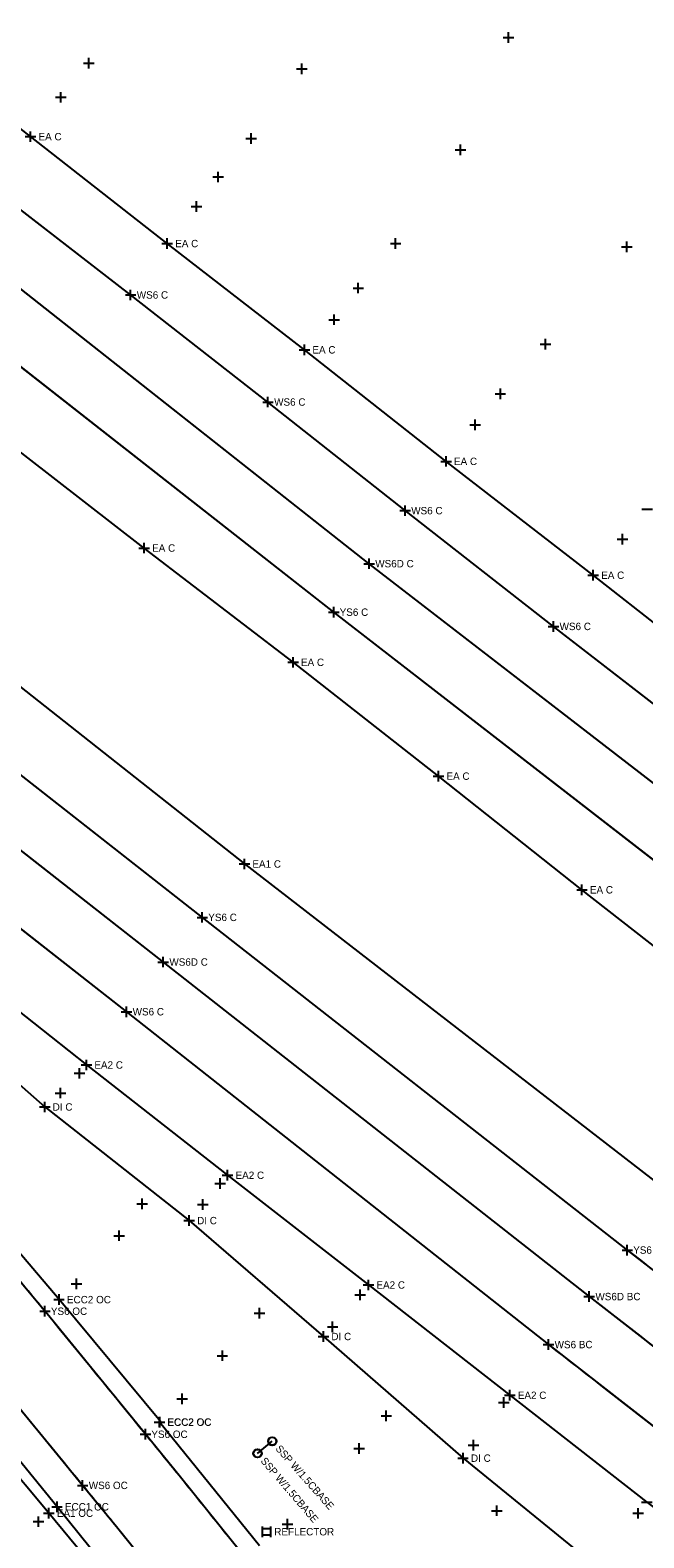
# Model space of a CAD drawing. Extents: x 1324236 to 1326110, y 459090 to 460782.
# Drawn here: x 1324752.2 to 1324868.3, y 460165.6 to 460451 of the extents above; entities that cross this region are included whole.
import ezdxf

# ---------------------------------------------------------------- set-up
doc = ezdxf.new("R2010")
doc.units = 0
for name, color, linetype in [('BD_X_Canopy', 7, 'Continuous'), ('DR_X_Ditch', 7, 'Continuous'), ('DR_X_Drive_Pipe', 7, 'Continuous'), ('DT_X_Contour_Minor', 7, 'Continuous'), ('DT_X_Terrain_Ground_Line', 7, 'Continuous'), ('DV_X_Property_Line', 7, 'Continuous'), ('PM_X_Edge_Line', 7, 'Continuous'), ('PM_X_Lane_Line', 7, 'Continuous'), ('PV_X_Shoulder', 7, 'Continuous'), ('RW_X_CL', 7, 'Continuous'), ('RW_X_Esmt_SH', 7, 'Continuous')]:
    doc.layers.add(name, color=color, linetype=linetype)

msp = doc.modelspace()

# ---------------------------------------------------------------- linework, layer by layer
at = {"layer": 'BD_X_Canopy'}
for points in [[(1324899.46, 460285.8), (1324816.32, 460350.02), (1324738, 460411.76), (1324655.48, 460475.52), (1324571, 460541.76), (1324483.76, 460609.87), (1324398.74, 460676.2), (1324371.29, 460697.8)], [(1324658.11, 460368.1), (1324700.58, 460334.74), (1324777.36, 460274.61), (1324857.99, 460211.28), (1324902.59, 460176.58)]]:
    msp.add_lwpolyline(points, dxfattribs=at)
at = {"layer": 'DR_X_Ditch'}
for points in [[(1324878.81, 460316.8), (1324851.22, 460338.14), (1324823.13, 460360.06), (1324797.18, 460380.62), (1324771.19, 460400.89), (1324745.05, 460421.13), (1324717.74, 460442.29), (1324690.08, 460463.98), (1324662.89, 460485.28), (1324634.89, 460507.31), (1324608, 460528.25), (1324578.82, 460551.06), (1324545.51, 460577.03), (1324519.35, 460597.5), (1324491.34, 460619.11), (1324462.72, 460641.59), (1324434.69, 460663.56), (1324406.17, 460685.88), (1324379.47, 460706.64)], [(1324891.6, 460277.31), (1324809.63, 460340.84), (1324730.77, 460402.67), (1324648.48, 460466.74), (1324563.88, 460532.79), (1324477.11, 460600.29), (1324390.8, 460667.51), (1324364.85, 460687.72)], [(1324662.39, 460379.05), (1324707.38, 460343.7), (1324784.75, 460283.06), (1324865.19, 460220.08), (1324910.42, 460185.13)], [(1324667.79, 460345.35), (1324692.77, 460325.94), (1324770.4, 460265.2), (1324850.27, 460202.19), (1324895.72, 460166.83)], [(1324792.82, 460161.93), (1324780.35, 460177.39), (1324780.35, 460177.39), (1324773.99, 460185.21), (1324773.99, 460185.21), (1324755.36, 460208.02), (1324755.36, 460208.02), (1324754.97, 460208.5), (1324754.97, 460208.5), (1324747.62, 460217.3)], [(1324780.95, 460152.26), (1324768.49, 460167.7), (1324768.49, 460167.7), (1324762.1, 460175.53), (1324762.1, 460175.53), (1324743.39, 460198.3)]]:
    msp.add_lwpolyline(points, dxfattribs=at)
for centre in [(1324795.2, 460181.59), (1324798, 460183.89)]:
    msp.add_circle(centre, 0.75, dxfattribs=at)
at = {"layer": 'DR_X_Drive_Pipe'}
for p, q in [((1324730.12, 460268.88), (1324754.93, 460247.17)), ((1324754.93, 460247.17), (1324782.27, 460225.66)), ((1324782.27, 460225.66), (1324807.67, 460203.72)), ((1324807.67, 460203.72), (1324834.1, 460180.69)), ((1324834.1, 460180.69), (1324858.57, 460160.78))]:
    msp.add_line(p, q, dxfattribs=at)
at = {"layer": 'DT_X_Contour_Minor'}
msp.add_line((1324795.2, 460181.59), (1324798, 460183.89), dxfattribs=at)
for centre in [(1324795.2, 460181.59), (1324798, 460183.89)]:
    msp.add_circle(centre, 0.8, dxfattribs=at)
at = {"layer": 'DT_X_Terrain_Ground_Line'}
for p, q in [((1324796.07, 460167.76), (1324796.07, 460165.76)), ((1324797.67, 460167.76), (1324797.67, 460165.76)), ((1324796.07, 460167.36), (1324797.67, 460167.36)), ((1324796.07, 460166.16), (1324797.67, 460166.16))]:
    msp.add_line(p, q, dxfattribs=at)
at = {"layer": 'DV_X_Property_Line'}
for p, q in [((1324751.25, 460430.86), (1324753.25, 460430.86)), ((1324752.25, 460429.86), (1324752.25, 460431.86)), ((1324777.12, 460410.62), (1324779.12, 460410.62)), ((1324778.12, 460409.62), (1324778.12, 460411.62)), ((1324803.09, 460390.5), (1324805.09, 460390.5)), ((1324804.09, 460389.5), (1324804.09, 460391.5)), ((1324830.89, 460368.39), (1324830.89, 460370.39)), ((1324829.89, 460369.39), (1324831.89, 460369.39)), ((1324773.75, 460351.98), (1324773.75, 460353.98)), ((1324772.75, 460352.98), (1324774.75, 460352.98)), ((1324857.75, 460347.83), (1324859.75, 460347.83)), ((1324858.75, 460346.83), (1324858.75, 460348.83)), ((1324800.93, 460331.35), (1324802.93, 460331.35)), ((1324801.93, 460330.35), (1324801.93, 460332.35)), ((1324829.47, 460308.8), (1324829.47, 460310.8)), ((1324828.47, 460309.8), (1324830.47, 460309.8)), ((1324792.73, 460292.17), (1324792.73, 460294.17)), ((1324791.73, 460293.17), (1324793.73, 460293.17)), ((1324855.61, 460288.28), (1324857.61, 460288.28)), ((1324856.61, 460287.28), (1324856.61, 460289.28)), ((1324762.82, 460254.12), (1324762.82, 460256.12)), ((1324761.82, 460255.12), (1324763.82, 460255.12)), ((1324788.54, 460234.24), (1324790.54, 460234.24)), ((1324789.54, 460233.24), (1324789.54, 460235.24)), ((1324815.21, 460213.47), (1324817.21, 460213.47)), ((1324816.21, 460212.47), (1324816.21, 460214.47)), ((1324756.63, 460210.7), (1324758.63, 460210.7)), ((1324757.63, 460209.7), (1324757.63, 460211.7)), ((1324842.97, 460191.59), (1324842.97, 460193.59)), ((1324841.97, 460192.59), (1324843.97, 460192.59)), ((1324776.63, 460186.53), (1324776.63, 460188.53)), ((1324776.68, 460186.48), (1324776.68, 460188.48)), ((1324775.63, 460187.53), (1324777.63, 460187.53)), ((1324775.68, 460187.48), (1324777.68, 460187.48)), ((1324755.72, 460169.27), (1324755.72, 460171.27)), ((1324756.25, 460171.48), (1324758.25, 460171.48)), ((1324757.25, 460170.48), (1324757.25, 460172.48)), ((1324867.9, 460172.35), (1324869.9, 460172.35)), ((1324754.72, 460170.27), (1324756.72, 460170.27))]:
    msp.add_line(p, q, dxfattribs=at)
for centre in [(1324795.2, 460181.59), (1324798, 460183.89)]:
    msp.add_circle(centre, 0.75, dxfattribs=at)
at = {"layer": 'PM_X_Edge_Line'}
for p, q in [((1324771.19, 460400.89), (1324745.05, 460421.13)), ((1324809.63, 460340.84), (1324730.77, 460402.67)), ((1324797.18, 460380.62), (1324771.19, 460400.89)), ((1324823.13, 460360.06), (1324797.18, 460380.62)), ((1324851.22, 460338.14), (1324823.13, 460360.06)), ((1324707.38, 460343.7), (1324784.75, 460283.06)), ((1324891.6, 460277.31), (1324809.63, 460340.84)), ((1324878.81, 460316.8), (1324851.22, 460338.14)), ((1324692.77, 460325.94), (1324770.4, 460265.2)), ((1324784.75, 460283.06), (1324865.19, 460220.08)), ((1324770.4, 460265.2), (1324850.27, 460202.19))]:
    msp.add_line(p, q, dxfattribs=at)
for centre, radius, start, end in [((1332942.31, 470626.47), 13173.19, 232.182468, 232.431095), ((1324072.68, 459646.74), 883.79, 39.46604, 40.2096), ((1324631.53, 460106.86), 159.89, 39.2438, 39.466), ((1045644.57, 232215.19), 360393.62, 39.2391323, 39.243813), ((1339553.55, 479051.8), 23905.95, 232.044663, 232.182676), ((1137214.55, 306139.37), 242695.74, 39.3968752, 39.4038325), ((1323156.76, 458864.4), 2088.05, 38.96246, 39.23913), ((1318476.8, 455079.72), 8106.84, 38.822046, 38.96246), ((1323603.67, 459224.1), 1499.06, 39.01053, 39.39688), ((1320278.85, 456530.7), 5777.94, 38.813749, 39.010535)]:
    msp.add_arc(centre, radius, start, end, dxfattribs=at)
at = {"layer": 'PM_X_Lane_Line'}
for p, q in [((1324816.32, 460350.02), (1324738, 460411.76)), ((1324899.46, 460285.8), (1324816.32, 460350.02)), ((1324700.58, 460334.74), (1324777.36, 460274.61)), ((1324777.36, 460274.61), (1324857.99, 460211.28))]:
    msp.add_line(p, q, dxfattribs=at)
msp.add_arc((1372700.01, 521641.35), 77862.13, 232.0883766, 232.1299606, dxfattribs=at)
at = {"layer": 'PV_X_Shoulder'}
for points in [[(1324884.45, 460266.49), (1324856.61, 460288.28), (1324829.47, 460309.8), (1324801.93, 460331.35), (1324773.75, 460352.98), (1324722.57, 460392.66), (1324640.21, 460456.72), (1324556.83, 460521.94), (1324468.66, 460590.9), (1324383.42, 460657.59), (1324356.31, 460678.35)], [(1324886.1, 460326.42), (1324858.75, 460347.83), (1324830.89, 460369.39), (1324804.09, 460390.5), (1324778.12, 460410.62), (1324752.25, 460430.86), (1324725.08, 460452.05), (1324697.48, 460473.35), (1324670.11, 460494.77), (1324642.41, 460516.54), (1324614.82, 460537.84), (1324586.12, 460559.97), (1324553.47, 460586.1), (1324557.53, 460592.81)], [(1324669.98, 460389.31), (1324715.86, 460353.85), (1324792.73, 460293.17), (1324872.96, 460231.13), (1324952.76, 460169.1), (1324978.52, 460148.79), (1325005.25, 460128.1), (1325032.05, 460107.12), (1325058.52, 460086.64), (1325084, 460067.05), (1325111.27, 460046.59)], [(1324649.53, 460330.5), (1324657.61, 460337.23), (1324685.43, 460316.01), (1324711.06, 460296.04), (1324736.02, 460276.35), (1324762.82, 460255.12), (1324789.54, 460234.24), (1324816.21, 460213.47), (1324842.97, 460192.59), (1324868.9, 460172.35), (1324896.06, 460152.06), (1324922.98, 460130.99), (1324949.48, 460111.07), (1324976.29, 460090.49), (1325004.33, 460071.45), (1325031.27, 460052.08), (1325058.13, 460031.85), (1325085.59, 460011.5)], [(1324795.55, 460164.06), (1324776.63, 460187.53), (1324776.68, 460187.49), (1324776.68, 460187.49), (1324776.68, 460187.48), (1324776.68, 460187.48), (1324776.84, 460187.48), (1324776.85, 460187.65), (1324776.85, 460187.65), (1324757.63, 460210.7), (1324757.63, 460210.7), (1324742.67, 460228.31)], [(1324763.53, 460163.74), (1324757.25, 460171.48), (1324757.25, 460171.48), (1324738.7, 460194.17)], [(1324762.3, 460162.23), (1324755.72, 460170.27), (1324755.72, 460170.27), (1324737.11, 460192.46)]]:
    msp.add_lwpolyline(points, dxfattribs=at)
at = {"layer": 'RW_X_CL'}
for p, q in [((1324842.71, 460448.63), (1324842.71, 460450.63)), ((1324841.71, 460449.63), (1324843.71, 460449.63)), ((1324762.26, 460444.75), (1324764.26, 460444.75)), ((1324763.26, 460443.75), (1324763.26, 460445.75)), ((1324803.58, 460442.69), (1324803.58, 460444.69)), ((1324802.58, 460443.69), (1324804.58, 460443.69)), ((1324757.96, 460437.31), (1324757.96, 460439.31)), ((1324756.96, 460438.31), (1324758.96, 460438.31)), ((1324792.99, 460430.51), (1324794.99, 460430.51)), ((1324793.99, 460429.51), (1324793.99, 460431.51)), ((1324832.64, 460428.35), (1324834.64, 460428.35)), ((1324833.64, 460427.35), (1324833.64, 460429.35)), ((1324786.76, 460423.23), (1324788.76, 460423.23)), ((1324787.76, 460422.23), (1324787.76, 460424.23)), ((1324782.67, 460417.63), (1324784.67, 460417.63)), ((1324783.67, 460416.63), (1324783.67, 460418.63)), ((1324820.34, 460410.62), (1324822.34, 460410.62)), ((1324821.34, 460409.62), (1324821.34, 460411.62)), ((1324865.12, 460408.98), (1324865.12, 460410.98)), ((1324864.12, 460409.98), (1324866.12, 460409.98)), ((1324771.19, 460399.89), (1324771.19, 460401.89)), ((1324813.28, 460402.2), (1324815.28, 460402.2)), ((1324814.28, 460401.2), (1324814.28, 460403.2)), ((1324770.19, 460400.89), (1324772.19, 460400.89)), ((1324808.73, 460396.21), (1324810.73, 460396.21)), ((1324809.73, 460395.21), (1324809.73, 460397.21)), ((1324848.71, 460391.58), (1324850.71, 460391.58)), ((1324849.71, 460390.58), (1324849.71, 460392.58)), ((1324840.16, 460382.17), (1324842.16, 460382.17)), ((1324841.16, 460381.17), (1324841.16, 460383.17)), ((1324796.18, 460380.62), (1324798.18, 460380.62)), ((1324797.18, 460379.62), (1324797.18, 460381.62)), ((1324835.38, 460376.32), (1324837.38, 460376.32)), ((1324836.38, 460375.32), (1324836.38, 460377.32)), ((1324822.13, 460360.06), (1324824.13, 460360.06)), ((1324823.13, 460359.06), (1324823.13, 460361.06)), ((1324867.96, 460360.31), (1324869.96, 460360.31)), ((1324863.3, 460354.67), (1324865.3, 460354.67)), ((1324864.3, 460353.67), (1324864.3, 460355.67)), ((1324816.32, 460349.02), (1324816.32, 460351.02)), ((1324815.32, 460350.02), (1324817.32, 460350.02)), ((1324809.63, 460339.84), (1324809.63, 460341.84)), ((1324808.63, 460340.84), (1324810.63, 460340.84)), ((1324851.22, 460337.14), (1324851.22, 460339.14)), ((1324850.22, 460338.14), (1324852.22, 460338.14)), ((1324783.75, 460283.06), (1324785.75, 460283.06)), ((1324784.75, 460282.06), (1324784.75, 460284.06)), ((1324776.36, 460274.61), (1324778.36, 460274.61)), ((1324777.36, 460273.61), (1324777.36, 460275.61)), ((1324769.4, 460265.2), (1324771.4, 460265.2)), ((1324770.4, 460264.2), (1324770.4, 460266.2)), ((1324760.51, 460253.54), (1324762.51, 460253.54)), ((1324761.51, 460252.54), (1324761.51, 460254.54)), ((1324757.92, 460248.81), (1324757.92, 460250.81)), ((1324756.92, 460249.81), (1324758.92, 460249.81)), ((1324788.14, 460231.67), (1324788.14, 460233.67)), ((1324787.14, 460232.67), (1324789.14, 460232.67)), ((1324772.37, 460228.82), (1324774.37, 460228.82)), ((1324773.37, 460227.82), (1324773.37, 460229.82)), ((1324783.87, 460228.69), (1324785.87, 460228.69)), ((1324784.87, 460227.69), (1324784.87, 460229.69)), ((1324768.02, 460222.8), (1324770.02, 460222.8)), ((1324769.02, 460221.8), (1324769.02, 460223.8)), ((1324864.19, 460220.08), (1324866.19, 460220.08)), ((1324865.19, 460219.08), (1324865.19, 460221.08)), ((1324759.93, 460213.7), (1324761.93, 460213.7)), ((1324760.93, 460212.7), (1324760.93, 460214.7)), ((1324813.61, 460211.62), (1324815.61, 460211.62)), ((1324814.61, 460210.62), (1324814.61, 460212.62)), ((1324856.99, 460211.28), (1324858.99, 460211.28)), ((1324857.99, 460210.28), (1324857.99, 460212.28)), ((1324753.97, 460208.5), (1324755.97, 460208.5)), ((1324754.97, 460207.5), (1324754.97, 460209.5)), ((1324794.57, 460208.12), (1324796.57, 460208.12)), ((1324795.57, 460207.12), (1324795.57, 460209.12)), ((1324808.42, 460205.54), (1324810.42, 460205.54)), ((1324809.42, 460204.54), (1324809.42, 460206.54)), ((1324849.27, 460202.19), (1324851.27, 460202.19)), ((1324850.27, 460201.19), (1324850.27, 460203.19)), ((1324787.55, 460200.08), (1324789.55, 460200.08)), ((1324788.55, 460199.08), (1324788.55, 460201.08)), ((1324779.93, 460191.91), (1324781.93, 460191.91)), ((1324780.93, 460190.91), (1324780.93, 460192.91)), ((1324840.81, 460191.24), (1324842.81, 460191.24)), ((1324841.81, 460190.24), (1324841.81, 460192.24)), ((1324818.58, 460188.71), (1324820.58, 460188.71)), ((1324819.58, 460187.71), (1324819.58, 460189.71)), ((1324772.99, 460185.21), (1324774.99, 460185.21)), ((1324773.99, 460184.21), (1324773.99, 460186.21)), ((1324813.43, 460182.53), (1324815.43, 460182.53)), ((1324814.43, 460181.53), (1324814.43, 460183.53)), ((1324835.1, 460183.15), (1324837.1, 460183.15)), ((1324836.1, 460182.15), (1324836.1, 460184.15)), ((1324762.1, 460174.53), (1324762.1, 460176.53)), ((1324761.1, 460175.53), (1324763.1, 460175.53)), ((1324839.49, 460170.74), (1324841.49, 460170.74)), ((1324840.49, 460169.74), (1324840.49, 460171.74)), ((1324867.26, 460169.25), (1324867.26, 460171.25)), ((1324752.73, 460168.67), (1324754.73, 460168.67)), ((1324753.73, 460167.67), (1324753.73, 460169.67)), ((1324799.89, 460168.21), (1324801.89, 460168.21)), ((1324800.89, 460167.21), (1324800.89, 460169.21)), ((1324866.26, 460170.25), (1324868.26, 460170.25))]:
    msp.add_line(p, q, dxfattribs=at)
at = {"layer": 'RW_X_Esmt_SH'}
for p, q in [((1324754.93, 460246.17), (1324754.93, 460248.17)), ((1324753.93, 460247.17), (1324755.93, 460247.17)), ((1324781.27, 460225.66), (1324783.27, 460225.66)), ((1324782.27, 460224.66), (1324782.27, 460226.66)), ((1324806.68, 460203.72), (1324808.68, 460203.72)), ((1324807.67, 460202.72), (1324807.67, 460204.72)), ((1324833.1, 460180.69), (1324835.1, 460180.69)), ((1324834.1, 460179.69), (1324834.1, 460181.69))]:
    msp.add_line(p, q, dxfattribs=at)

# ---------------------------------------------------------------- texts
at = {"layer": 'DT_X_Contour_Minor'}
for rotation, p in [(311.4379, (1324798.51, 460182.41)), (310.5516, (1324795.69, 460180.1))]:
    msp.add_text('SSP W/1.5CBASE', height=1.4, rotation=rotation, dxfattribs=at).set_placement(p)
at = {"layer": 'DV_X_Property_Line'}
for s, p in [('EA C', (1324753.75, 460430.16)), ('EA C', (1324779.62, 460409.92)), ('EA C', (1324805.59, 460389.8)), ('EA C', (1324832.39, 460368.69)), ('EA C', (1324775.25, 460352.28)), ('EA C', (1324860.25, 460347.13)), ('EA C', (1324803.43, 460330.65)), ('EA C', (1324830.97, 460309.1)), ('EA1 C', (1324794.23, 460292.47)), ('EA C', (1324858.11, 460287.58)), ('EA2 C', (1324764.32, 460254.42)), ('EA2 C', (1324791.04, 460233.54)), ('EA2 C', (1324817.71, 460212.77)), ('ECC2 OC', (1324759.13, 460210)), ('EA2 C', (1324844.47, 460191.89)), ('ECC2 OC', (1324778.13, 460186.83)), ('ECC2 OC', (1324778.18, 460186.78)), ('EA1 OC', (1324757.22, 460169.57)), ('ECC1 OC', (1324758.75, 460170.78))]:
    msp.add_text(s, height=1.4, dxfattribs=at).set_placement(p)
at = {"layer": 'RW_X_CL'}
for s, p in [('WS6 C', (1324772.35, 460400.19)), ('WS6 C', (1324798.35, 460379.92)), ('WS6 C', (1324824.3, 460359.36)), ('WS6D C', (1324817.49, 460349.32)), ('YS6 C', (1324810.75, 460340.14)), ('WS6 C', (1324852.38, 460337.44)), ('YS6 C', (1324785.88, 460282.36)), ('WS6D C', (1324778.52, 460273.91)), ('WS6 C', (1324771.57, 460264.5)), ('YS6 BC', (1324866.31, 460219.38)), ('WS6D BC', (1324859.16, 460210.58)), ('YS6 OC', (1324756.09, 460207.8)), ('WS6 BC', (1324851.44, 460201.49)), ('YS6 OC', (1324775.11, 460184.51)), ('WS6 OC', (1324763.26, 460174.83))]:
    msp.add_text(s, height=1.4, dxfattribs=at).set_placement(p)
at = {"layer": 'RW_X_Esmt_SH'}
for s, p in [('DI C', (1324756.43, 460246.47)), ('DI C', (1324783.77, 460224.96)), ('DI C', (1324809.18, 460203.02)), ('DI C', (1324835.6, 460179.99)), ('REFLECTOR', (1324798.37, 460166.06))]:
    msp.add_text(s, height=1.4, dxfattribs=at).set_placement(p)

doc.saveas('drawing.dxf')
